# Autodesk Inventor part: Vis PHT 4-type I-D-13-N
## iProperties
Created: 2011-01
Part Number: Vis PHT 4-type I-D-13-N
Document SubType Name: Modeling
Designer: eric
Density: 1 g/cm^3
Mass: 0.26944 g
Surface Area: 3.48768 cm^2
Volume: 0.26944 cm^3
Author: eric
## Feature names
1. Base1
